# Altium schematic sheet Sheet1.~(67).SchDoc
size A4; SheetNumber: 1; SheetTotal: 1
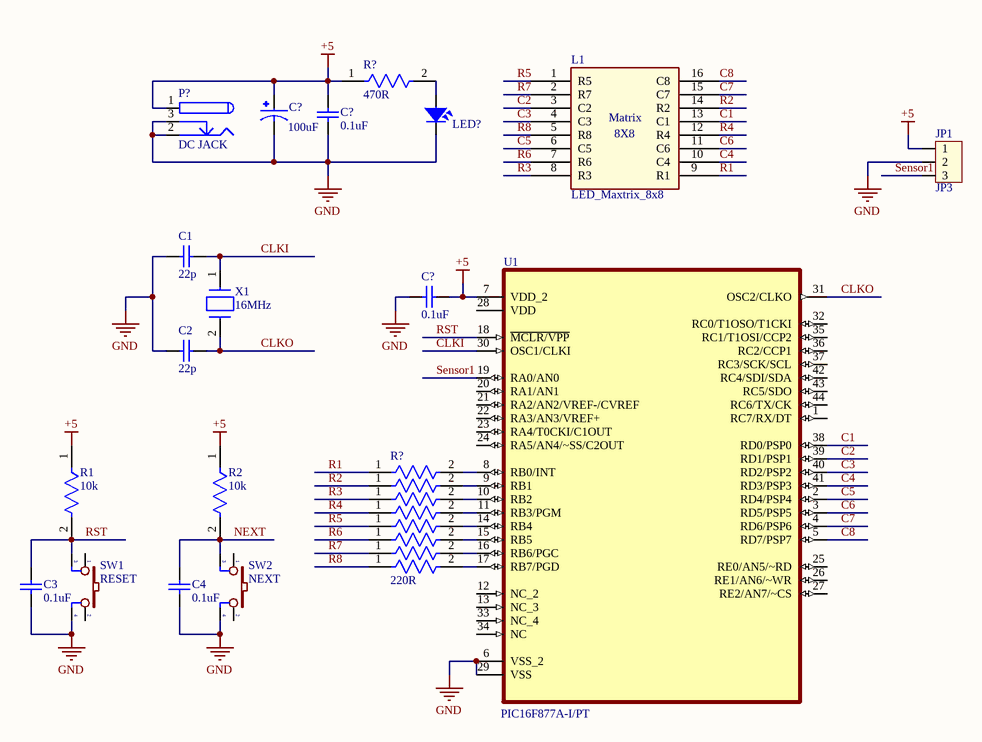
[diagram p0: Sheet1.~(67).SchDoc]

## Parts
(Parts that share a designator on the sheet are numbered #1, #2 ... from top to bottom, then left to right.)
C1  22p  [CAPC2013X94X50LL25T25]
C2  22p  [CAPC2013X94X50LL25T25]
C3  0.1uF  [CAPC2013X94X50LL25T25]
C4  0.1uF  [CAPC2013X94X50LL25T25]
C?#1  value 100uF  [FP-FKF-MFG]  (hidden comment: EEE-FK1H101GP)
C?#2  0.1uF  [CAPC2013X94X50LL25T25]
C?#3  0.1uF  [CAPC2013X94X50LL25T25]
JP1  JP3  [CON3]
L1  LED_Maxtrix_8x8  [LED_Matrix_8x8]
LED?  LED SMD  [SM-LED-0805-Green]  (value not drawn)
P?  DC JACK  [DC5.5/2.1]
R1  10k  [FP-CR0805-MFG]
R2  10k  [FP-CR0805-MFG]
R?#1  470R  [FP-CR0805-IPC_A]
R?#2  220R  [FP-CR0805-IPC_A]  (value not drawn)
R?#3  220R  [FP-CR0805-IPC_A]  (value not drawn)
R?#4  220R  [FP-CR0805-IPC_A]  (value not drawn)
R?#5  220R  [FP-CR0805-IPC_A]  (value not drawn)
R?#6  220R  [FP-CR0805-IPC_A]  (value not drawn)
R?#7  220R  [FP-CR0805-IPC_A]  (value not drawn)
R?#8  220R  [FP-CR0805-IPC_A]  (value not drawn)
R?#9  220R  [FP-CR0805-IPC_A]
SW1  RESET  [SW4]
SW2  NEXT  [SW4]
U1  PIC16F877A-I/PT  [TQFP-44]
X1  16MHz  [FP-ABM7-MFG]

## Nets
+5: C?#1.1 C?#2.2 C?#3.2 JP1.1 P?.1 R1.1 R2.1 R?#1.1 U1.7(VDD_2)
GND: C1.1 C2.1 C3.1 C4.1 C?#1.2 C?#2.1 C?#3.1 JP1.2 LED?.2 P?.2 P?.3 SW1.4 SW2.4 U1.6(VSS_2) U1.29(VSS)
C1: L1.13(C1) U1.38(RD0/PSP0)
C2: L1.3(C2) U1.39(RD1/PSP1)
C3: L1.4(C3) U1.40(RD2/PSP2)
C4: L1.10(C4) U1.41(RD3/PSP3)
C5: L1.6(C5) U1.2(RD4/PSP4)
C6: L1.11(C6) U1.3(RD5/PSP5)
C7: L1.15(C7) U1.4(RD6/PSP6)
C8: L1.16(C8) U1.5(RD7/PSP7)
CLKI: C1.2 U1.30(OSC1/CLKI) X1.1
CLKO: C2.2 U1.31(OSC2/CLKO) X1.2
NEXT: C4.2 R2.2 SW2.3
R1: L1.9(R1) R?#2.1
R2: L1.14(R2) R?#3.1
R3: L1.8(R3) R?#4.1
R4: L1.12(R4) R?#5.1
R5: L1.1(R5) R?#6.1
R6: L1.7(R6) R?#7.1
R7: L1.2(R7) R?#8.1
R8: L1.5(R8) R?#9.1
RST: C3.2 R1.2 SW1.3 U1.18(~{MCLR/VPP})
Sensor1: JP1.3 U1.19(RA0/AN0)
NetLED?_1: LED?.1 R?#1.2
NetR?#2_2: R?#2.2 U1.8(RB0/INT)
NetR?#3_2: R?#3.2 U1.9(RB1)
NetR?#4_2: R?#4.2 U1.10(RB2)
NetR?#5_2: R?#5.2 U1.11(RB3/PGM)
NetR?#6_2: R?#6.2 U1.14(RB4)
NetR?#7_2: R?#7.2 U1.15(RB5)
NetR?#8_2: R?#8.2 U1.16(RB6/PGC)
NetR?#9_2: R?#9.2 U1.17(RB7/PGD)

Not connected (* = marked no-connect by the designer): SW1 1 2; SW2 1 2; U1 1(RC7/RX/DT) 12(NC_2) 13(NC_3) 20(RA1/AN1) 21(RA2/AN2/VREF-/CVREF) 22(RA3/AN3/VREF+) 23(RA4/T0CKI/C1OUT) 24(RA5/AN4/~SS/C2OUT) 25(RE0/AN5/~RD) 26(RE1/AN6/~WR) 27(RE2/AN7/~CS) 28(VDD) 32(RC0/T1OSO/T1CKI) 33(NC_4) 34(NC) 35(RC1/T1OSI/CCP2) 36(RC2/CCP1) 37(RC3/SCK/SCL) 42(RC4/SDI/SDA) 43(RC5/SDO) 44(RC6/TX/CK)

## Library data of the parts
C1-C4 C?#2 C?#3 = LD051C104KAB2A: Cap Ceramic 0.1uF 100V X7R 10% SMD 0805 125°C Embossed T/R; Manufacturer: Kyocera AVX; Value: 100nF
C?#1 = EEE-FK1H101GP: Cap Aluminum 100uF 50V 20% (8 X 10.2mm) SMD 350mA 5000 hr 105°C T/R; Manufacturer: Panasonic; Life (Hours): 5000Hour; Leakage Current: 10mA; Impedance: 340mR
JP1 = Con3: Connector 3
LED? = LED-SMD-0805
P? = DC5.5/2.1: Low Voltage Power Supply Connector; Solder: WAVE
R1 R2 R?#1-R?#9 = CR0805-JW-331ELF: Res Thick Film 0805 330 Ohm 5% 1/8W ±200ppm/°C Molded SMD SMD Paper Tape on Plastic Reel; Manufacturer: Bourns; Value: 330R; Power Rating: 125mW; Voltage Rating: 150V
SW1 SW2 = SW4-1: Switch button 4 pin; Value: SW chip 4 pin
U1 = PIC16F877A-I/PT: PIC16F877A Microcontroller IC 8-Bit 20MHz 14KB _8K x 14_ FLASH 44-TQFP _10x10_; MF: Microchip
X1 = ABM7-16.000MHZ-4-T: Crystal 16MHz ±30ppm (Tol) ±50ppm (Stability) 18pF FUND 50Ohm 2-Pin Mini-CSMD T/R; Manufacturer: Abracon; ESR (Equivalent Series Resistance): 50R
